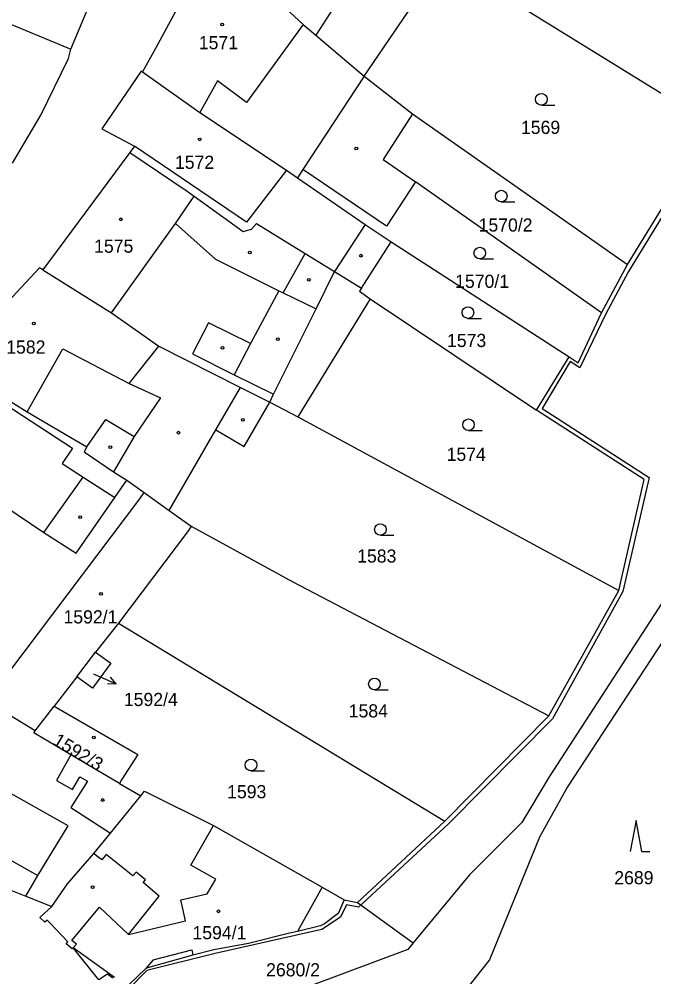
# Model space of a CAD drawing. Extents: x -600849 to -599899, y -1204328 to -1203436.
# Drawn here: x -600410.5 to -600328.6, y -1204152.5 to -1204028.8 of the extents above; entities that cross this region are included whole.
import ezdxf

# ---------------------------------------------------------------- set-up
doc = ezdxf.new("R2010")
doc.units = 0
for name, color, linetype in [('Vrstva 1', 7, 'Continuous'), ('Vrstva 2', 7, 'Continuous'), ('Vrstva 3', 7, 'Continuous'), ('Vrstva 4', 7, 'Continuous'), ('Vrstva 5', 7, 'Continuous'), ('Vrstva 7', 7, 'Continuous')]:
    doc.layers.add(name, color=color, linetype=linetype)

msp = doc.modelspace()

# ---------------------------------------------------------------- linework, layer by layer
at = {"layer": 'Vrstva 1'}
for p, q in [((-600403.83, -1204032.65), (-600396.6, -1204015.37)), ((-600366, -1204036.13), (-600355.69, -1204020.98)), ((-600355.69, -1204020.98), (-600321.02, -1204042.49)), ((-600366, -1204036.13), (-600359.74, -1204041.01)), ((-600359.74, -1204041.01), (-600332.03, -1204060.46)), ((-600332.03, -1204060.46), (-600321.02, -1204042.49)), ((-600395.63, -1204045.2), (-600396.22, -1204046)), ((-600396.22, -1204046), (-600407.43, -1204061.16)), ((-600396.22, -1204046), (-600388.84, -1204051)), ((-600376, -1204048.29), (-600374.58, -1204049.28)), ((-600335.36, -1204066.7), (-600359.38, -1204049.79)), ((-600366.33, -1204063.51), (-600362.51, -1204057.56)), ((-600362.51, -1204057.56), (-600339.54, -1204072.41)), ((-600335.36, -1204066.7), (-600332.03, -1204060.46)), ((-600365.22, -1204064.92), (-600374.53, -1204080.15)), ((-600365.22, -1204064.92), (-600343.76, -1204079.3)), ((-600343.76, -1204079.3), (-600339.54, -1204072.41)), ((-600378.18, -1204078.26), (-600374.53, -1204080.15)), ((-600374.53, -1204080.15), (-600333.15, -1204102.57)), ((-600403.33, -1204083.11), (-600401.79, -1204084.03)), ((-600391.15, -1204092.25), (-600388.29, -1204094.25)), ((-600342.15, -1204118.75), (-600333.15, -1204102.57)), ((-600397.67, -1204106.79), (-600400.65, -1204110.56)), ((-600397.67, -1204106.79), (-600355.59, -1204132.36)), ((-600403.08, -1204113.74), (-600400.65, -1204110.56)), ((-600403.08, -1204113.74), (-600405.98, -1204117.53)), ((-600408.45, -1204120.72), (-600416.08, -1204116)), ((-600408.45, -1204120.72), (-600405.98, -1204117.53)), ((-600355.59, -1204132.36), (-600342.15, -1204118.75)), ((-600408.61, -1204120.97), (-600408.45, -1204120.72)), ((-600397.57, -1204127.49), (-600394.82, -1204129.11)), ((-600435.03, -1204132.18), (-600409.63, -1204142.04)), ((-600366.87, -1204142.89), (-600355.59, -1204132.36)), ((-600352.39, -1204139.29), (-600359.65, -1204148.07)), ((-600409.63, -1204142.04), (-600408.08, -1204139.4)), ((-600406.3, -1204143.38), (-600404.25, -1204140.47)), ((-600409.63, -1204142.04), (-600406.3, -1204143.38)), ((-600368.58, -1204142.52), (-600366.87, -1204142.89)), ((-600366.87, -1204142.89), (-600359.65, -1204148.07)), ((-600360.37, -1204148.94), (-600380.71, -1204156.53)), ((-600359.65, -1204148.07), (-600360.37, -1204148.94))]:
    msp.add_line(p, q, dxfattribs=at)
for points in [[(-600422.45, -1204020.24), (-600417.38, -1204024.67), (-600412.83, -1204028.39), (-600413.07, -1204028.85), (-600403.83, -1204032.65)], [(-600385.9, -1204019.58), (-600392.89, -1204032.59), (-600394.6, -1204035.6)], [(-600385.9, -1204019.58), (-600381.9, -1204021.98), (-600373.88, -1204029.46), (-600372.23, -1204030.86), (-600371.35, -1204031.6), (-600366, -1204036.13)], [(-600411.37, -1204047.38), (-600407.7, -1204041.18), (-600404.14, -1204033.88), (-600403.83, -1204032.65)], [(-600290.25, -1204033.5), (-600306.04, -1204051.89), (-600313.29, -1204075.32), (-600317.59, -1204085.78), (-600317.98, -1204087.21), (-600318.67, -1204088.6), (-600321.71, -1204093.84), (-600326.01, -1204101.77), (-600342.13, -1204126.63), (-600345.65, -1204132.55), (-600352.39, -1204139.29)], [(-600394.6, -1204035.6), (-600394.77, -1204035.51), (-600399.82, -1204042.95), (-600395.63, -1204045.2)], [(-600394.6, -1204035.6), (-600387.17, -1204040.84), (-600376, -1204048.29)], [(-600359.74, -1204041.01), (-600363.55, -1204046.9), (-600359.38, -1204049.79)], [(-600359.38, -1204049.79), (-600363.12, -1204055.51), (-600373.89, -1204048.2), (-600374.58, -1204049.28)], [(-600374.58, -1204049.28), (-600365.85, -1204055.29), (-600362.51, -1204057.56)], [(-600388.84, -1204051), (-600387.92, -1204051.66), (-600381.58, -1204056.2), (-600380.51, -1204055.9), (-600379.86, -1204055.17), (-600373.58, -1204059.05), (-600369.8, -1204061.39), (-600366.33, -1204063.51)], [(-600407.43, -1204061.16), (-600407.88, -1204060.92), (-600419.53, -1204073.4)], [(-600407.43, -1204061.16), (-600398.59, -1204066.73), (-600392.47, -1204071), (-600381.93, -1204076.36), (-600378.18, -1204078.26)], [(-600366.33, -1204063.51), (-600366.6, -1204063.93), (-600365.22, -1204064.92)], [(-600339.54, -1204072.41), (-600338.36, -1204073.16), (-600335.36, -1204066.7)], [(-600418.11, -1204074.1), (-600409.45, -1204079.49), (-600403.33, -1204083.11)], [(-600391.15, -1204092.25), (-600385.12, -1204081.83), (-600381.48, -1204083.96), (-600378.18, -1204078.26)], [(-600333.15, -1204102.57), (-600329.87, -1204088.25), (-600343.76, -1204079.3)], [(-600401.79, -1204084.03), (-600402.11, -1204084.68), (-600398.33, -1204087.25), (-600396.63, -1204088.33)], [(-600427.57, -1204087.6), (-600422.27, -1204091.18), (-600423.26, -1204092.46), (-600419.74, -1204095.21), (-600418.29, -1204096.42), (-600416.86, -1204094.43), (-600415.52, -1204093.48), (-600415.04, -1204091.5), (-600414.1, -1204090.54), (-600407.31, -1204095.09), (-600403.13, -1204097.75), (-600398.16, -1204090.55), (-600396.63, -1204088.33)], [(-600396.63, -1204088.33), (-600394.39, -1204089.93), (-600391.15, -1204092.25)], [(-600388.29, -1204094.25), (-600388.67, -1204094.84), (-600397.67, -1204106.79)], [(-600388.29, -1204094.25), (-600375.2, -1204101.47), (-600342.15, -1204118.75)], [(-600318.83, -1204095.44), (-600323.56, -1204103.14), (-600339.77, -1204127.94), (-600343.37, -1204134.43), (-600349.81, -1204150.29)], [(-600400.65, -1204110.56), (-600398.67, -1204111.98), (-600401.06, -1204115.2), (-600403.08, -1204113.74)], [(-600405.98, -1204117.53), (-600395.2, -1204123.76), (-600397.29, -1204127.01), (-600397.57, -1204127.49)], [(-600397.57, -1204127.49), (-600403.83, -1204123.79), (-600408.61, -1204120.97)], [(-600421.09, -1204123.47), (-600424.32, -1204130.25), (-600408.08, -1204139.4)], [(-600408.08, -1204139.4), (-600404.18, -1204132.95), (-600421.09, -1204123.47)], [(-600404.25, -1204140.47), (-600400.88, -1204136.56), (-600398.72, -1204133.91), (-600394.82, -1204129.11)], [(-600394.82, -1204129.11), (-600394.33, -1204128.5), (-600385.44, -1204132.91), (-600371.4, -1204140.9), (-600368.58, -1204142.52)], [(-600368.58, -1204142.52), (-600369.36, -1204144.27), (-600371.09, -1204145.61), (-600371.61, -1204145.89), (-600374.61, -1204146.61), (-600375.62, -1204146.85)], [(-600398.43, -1204152.63), (-600399.09, -1204152.13), (-600400.21, -1204152.86), (-600403.54, -1204148.72), (-600403.65, -1204148.84), (-600404.45, -1204148.21), (-600404.24, -1204147.94), (-600406.51, -1204145.53), (-600406.9, -1204145.15), (-600407.17, -1204145.4), (-600407.82, -1204144.8), (-600406.3, -1204143.38)], [(-600375.62, -1204146.85), (-600380.92, -1204148.17), (-600385.4, -1204149)], [(-600385.4, -1204149), (-600388.1, -1204149.68), (-600393.93, -1204151.3), (-600394.16, -1204151.38), (-600396.34, -1204153.52), (-600396.43, -1204153.62)], [(-600349.81, -1204150.29), (-600353.78, -1204155.29), (-600353.11, -1204156.12)]]:
    msp.add_lwpolyline(points, dxfattribs=at)
at = {"layer": 'Vrstva 3'}
for p, q in [((-600343.13, -1204039.89), (-600341.38, -1204039.89)), ((-600348.3, -1204052.39), (-600346.55, -1204052.39)), ((-600351.07, -1204059.74), (-600349.32, -1204059.74)), ((-600352.6, -1204067.43), (-600350.85, -1204067.43)), ((-600352.53, -1204081.91), (-600350.78, -1204081.91)), ((-600363.9, -1204095.45), (-600362.15, -1204095.45)), ((-600364.66, -1204115.4), (-600362.91, -1204115.4)), ((-600380.59, -1204125.86), (-600378.84, -1204125.86)), ((-600330.9, -1204132.28), (-600331.65, -1204136.28)), ((-600330.15, -1204136.28), (-600330.9, -1204132.28)), ((-600330.15, -1204136.28), (-600329.15, -1204136.28))]:
    msp.add_line(p, q, dxfattribs=at)
for centre in [(-600343.13, -1204039.14), (-600348.3, -1204051.64), (-600351.07, -1204058.99), (-600352.6, -1204066.68), (-600352.53, -1204081.16), (-600363.9, -1204094.7), (-600364.66, -1204114.65), (-600380.59, -1204125.11)]:
    msp.add_circle(centre, 0.75, dxfattribs=at)
at = {"layer": 'Vrstva 4'}
for p, q in [((-600365.84, -1204020.87), (-600372.23, -1204030.86)), ((-600373.88, -1204029.46), (-600381.19, -1204039.54)), ((-600366, -1204036.13), (-600373.89, -1204048.2)), ((-600384.93, -1204036.77), (-600387.17, -1204040.84)), ((-600381.19, -1204039.54), (-600384.93, -1204036.77)), ((-600320.55, -1204042.75), (-600331.89, -1204061.39)), ((-600381.15, -1204054.99), (-600395.63, -1204045.2)), ((-600376, -1204048.29), (-600381.15, -1204054.99)), ((-600390.32, -1204055.18), (-600387.92, -1204051.66)), ((-600398.59, -1204066.73), (-600390.32, -1204055.18)), ((-600390.32, -1204055.18), (-600385.15, -1204059.78)), ((-600365.85, -1204055.29), (-600369.8, -1204061.39)), ((-600385.15, -1204059.78), (-600376.99, -1204063.86)), ((-600376.44, -1204064.13), (-600373.58, -1204059.05)), ((-600372.2, -1204066.21), (-600369.8, -1204061.39)), ((-600331.89, -1204061.39), (-600334.82, -1204066.84)), ((-600376.99, -1204063.86), (-600380.66, -1204070.67)), ((-600376.99, -1204063.86), (-600376.44, -1204064.13)), ((-600376.44, -1204064.13), (-600372.2, -1204066.21)), ((-600377.67, -1204077.22), (-600372.2, -1204066.21)), ((-600334.82, -1204066.84), (-600338.16, -1204073.81)), ((-600386.09, -1204068), (-600388.15, -1204072.03)), ((-600380.66, -1204070.67), (-600386.09, -1204068)), ((-600396.3, -1204075.83), (-600392.47, -1204071)), ((-600380.66, -1204070.67), (-600382.75, -1204074.7)), ((-600409.45, -1204079.49), (-600404.86, -1204071.35)), ((-600404.86, -1204071.35), (-600396.3, -1204075.83)), ((-600388.15, -1204072.03), (-600382.75, -1204074.7)), ((-600339.39, -1204073.02), (-600343.02, -1204079.09)), ((-600338.16, -1204073.81), (-600339.39, -1204073.02)), ((-600418.42, -1204074.54), (-600403.62, -1204084.2)), ((-600382.75, -1204074.7), (-600377.67, -1204077.22)), ((-600396.3, -1204075.83), (-600392.26, -1204077.69)), ((-600385.12, -1204081.83), (-600381.93, -1204076.36)), ((-600378.18, -1204078.26), (-600377.67, -1204077.22)), ((-600392.26, -1204077.69), (-600395.66, -1204082.69)), ((-600343.02, -1204079.09), (-600329.23, -1204087.98)), ((-600401.79, -1204084.03), (-600399.31, -1204080.49)), ((-600399.31, -1204080.49), (-600395.66, -1204082.69)), ((-600395.66, -1204082.69), (-600398.33, -1204087.25)), ((-600403.62, -1204084.2), (-600404.96, -1204086.19)), ((-600404.96, -1204086.19), (-600402.23, -1204087.94)), ((-600407.31, -1204095.09), (-600402.23, -1204087.94)), ((-600402.23, -1204087.94), (-600398.16, -1204090.55)), ((-600329.23, -1204087.98), (-600332.61, -1204102.71)), ((-600411.72, -1204112.98), (-600394.95, -1204090.73)), ((-600394.95, -1204090.73), (-600394.39, -1204089.93)), ((-600332.61, -1204102.71), (-600341.7, -1204119.16)), ((-600341.7, -1204119.16), (-600355.11, -1204132.71)), ((-600403.83, -1204123.79), (-600405.68, -1204127.12)), ((-600403.6, -1204128.28), (-600402.67, -1204126.62)), ((-600402.67, -1204126.62), (-600401.7, -1204127.22)), ((-600405.68, -1204127.12), (-600403.6, -1204128.28)), ((-600401.7, -1204127.22), (-600403.85, -1204130.59)), ((-600403.85, -1204130.59), (-600398.72, -1204133.91)), ((-600388.35, -1204138.05), (-600385.44, -1204132.91)), ((-600355.11, -1204132.71), (-600366.74, -1204143.47)), ((-600400.52, -1204136.83), (-600400.88, -1204136.56)), ((-600399.82, -1204137.34), (-600400.52, -1204136.83)), ((-600399.29, -1204136.67), (-600399.82, -1204137.34)), ((-600395.83, -1204139.44), (-600399.29, -1204136.67)), ((-600385.11, -1204139.86), (-600388.35, -1204138.05)), ((-600395.4, -1204138.95), (-600395.83, -1204139.44)), ((-600394.21, -1204139.93), (-600395.4, -1204138.95)), ((-600394.51, -1204140.29), (-600394.21, -1204139.93)), ((-600392.42, -1204142.05), (-600394.51, -1204140.29)), ((-600386.23, -1204141.74), (-600385.11, -1204139.86)), ((-600389.64, -1204142.54), (-600386.23, -1204141.74)), ((-600371.4, -1204140.9), (-600374.61, -1204146.61)), ((-600396.4, -1204147.02), (-600392.42, -1204142.05)), ((-600389.06, -1204145.22), (-600389.64, -1204142.54)), ((-600403.72, -1204147.76), (-600400.14, -1204143.47)), ((-600400.14, -1204143.47), (-600396.4, -1204147.02)), ((-600368.27, -1204143.18), (-600369.05, -1204144.78)), ((-600366.74, -1204143.47), (-600368.27, -1204143.18)), ((-600396.4, -1204147.02), (-600389.06, -1204145.22)), ((-600369.05, -1204144.78), (-600371.43, -1204146.37)), ((-600371.43, -1204146.37), (-600385.22, -1204149.45)), ((-600403.11, -1204148.26), (-600403.72, -1204147.76)), ((-600403.54, -1204148.72), (-600403.11, -1204148.26)), ((-600398.18, -1204152.56), (-600403.54, -1204148.72)), ((-600393.23, -1204150.27), (-600388.23, -1204149)), ((-600388.23, -1204149), (-600388.1, -1204149.68)), ((-600393.23, -1204150.27), (-600394.16, -1204151.38)), ((-600385.22, -1204149.45), (-600394.01, -1204151.67)), ((-600394.01, -1204151.67), (-600396.53, -1204154.19))]:
    msp.add_line(p, q, dxfattribs=at)
at = {"layer": 'Vrstva 5'}
for centre in [(-600384.32, -1204029.46), (-600387.21, -1204044.31), (-600367, -1204045.49), (-600397.4, -1204054.64), (-600380.73, -1204058.91), (-600366.4, -1204059.33), (-600373.12, -1204062.44), (-600408.62, -1204068.08), (-600377.13, -1204070.13), (-600384.27, -1204071.24), (-600381.63, -1204080.52), (-600389.94, -1204082.19), (-600398.74, -1204084.06), (-600402.62, -1204093.1), (-600399.94, -1204103), (-600400.87, -1204121.56), (-600399.73, -1204129.63), (-600401.02, -1204140.9), (-600384.77, -1204144.01)]:
    msp.add_circle(centre, 0.175, dxfattribs=at)
at = {"layer": 'Vrstva 7'}
for p, q in [((-600400.91, -1204113.34), (-600400.73, -1204113.42)), ((-600400.73, -1204113.42), (-600397.99, -1204114.64)), ((-600397.99, -1204114.64), (-600398.7, -1204113.78)), ((-600397.99, -1204114.64), (-600399.11, -1204114.69))]:
    msp.add_line(p, q, dxfattribs=at)

# ---------------------------------------------------------------- texts
at = {"layer": 'Vrstva 2'}
for s, p in [('1571', (-600387.32, -1204032.67)), ('1569', (-600345.76, -1204043.61)), ('1572', (-600390.4, -1204048.12)), ('1570/2', (-600351.22, -1204056.22)), ('1575', (-600400.83, -1204058.95)), ('1570/1', (-600354.25, -1204063.49)), ('1573', (-600355.3, -1204071.13)), ('1582', (-600412.17, -1204071.98)), ('1574', (-600355.35, -1204085.83)), ('1583', (-600366.89, -1204098.97)), ('1592/1', (-600404.78, -1204106.83)), ('1592/4', (-600396.99, -1204117.5)), ('1584', (-600367.98, -1204118.97)), ('1593', (-600383.67, -1204129.41)), ('2689', (-600333.72, -1204140.52)), ('1594/1', (-600388.14, -1204147.62)), ('2680/2', (-600378.64, -1204152.41))]:
    msp.add_text(s, height=1.7, dxfattribs=at).set_placement(p)
msp.add_text('1592/3', height=1.7, rotation=329, dxfattribs=at).set_placement((-600406.29, -1204122.36))

doc.saveas('drawing.dxf')
